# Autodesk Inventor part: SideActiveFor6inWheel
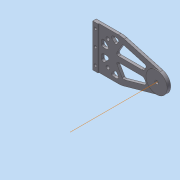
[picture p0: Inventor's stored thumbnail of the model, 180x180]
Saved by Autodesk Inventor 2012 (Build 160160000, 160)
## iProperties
Created: 2011-12
Part Number: SideActiveFor6inWheel
Document SubType Name: Modeling
Designer: OSR
Density: 2.71 g/cm^3
Material: Aluminum-6061
Mass: 81.6285 g
Surface Area: 165.271 cm^2
Volume: 30.1212 cm^3
Author: OSR
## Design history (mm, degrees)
sketch "Sketch1"
  geometry: L1 (0, 0)-(0, 76.2); L2 (0, 76.2)-(44.45, 76.2); L3 (54.781, 74.772)-(119.868, 56.436); L4 (119.868, 19.764)-(54.781, 1.428); L5 (44.45, 0)-(0, 0); L6 (114.702, 38.1)-(0, 38.1); A1 r 19.05 centre (114.702, 38.1) between (119.868, 19.764) and (119.868, 56.436); A2 r 38.1 centre (44.45, 38.1) between (54.781, 74.772) and (44.45, 76.2); A3 r 38.1 centre (44.45, 38.1) between (44.45, 0) and (54.781, 1.428)
  constraints: 12 end point, 6 point on circle, 6 tangent, 3 centre point, 2 parallel, 1 concentric, 1 horizontal, 1 midpoint, 1 perpendicular, 1 vertical
  dimensions: "d0" = 76.2 distance of L1.start L1.end; "d1" = 114.7022 distance of L6.start L6.end; "d2" = 38.1 radius of A2; "d3" = 44.45 distance of L1.end L2.end; "d4" = 38.1 diameter of A1
extrude "Extrusion1" new body sketch "Sketch1" distance "d5" = 6.35; taper "d6" = 0 deg
sketch "Sketch2"
  geometry: L1 (0, 0)-(0, 76.2) reference; L2 (44.45, 0)-(0, 0) reference; L3 (119.868, 19.764)-(54.781, 1.428) reference; L4 (54.781, 74.772)-(119.868, 56.436) reference; L5 (0, 76.2)-(44.45, 76.2) reference; L6 (9.525, 76.2)-(9.525, 0); A1 r 38.1 centre (44.45, 38.1) between (44.45, 0) and (54.781, 1.428) reference; A2 r 19.05 centre (114.702, 38.1) between (119.868, 19.764) and (119.868, 56.436) reference; A3 r 38.1 centre (44.45, 38.1) between (54.781, 74.772) and (44.45, 76.2) reference; 1 further point
  constraints: 2 end point, 2 point on line, 1 coincident, 1 perpendicular, 3 other
  dimensions: "d7" = 9.525 distance between parallel lines of L1 L6
extrude "Extrusion2" cut sketch "Sketch2" distance "d8" = 1.5875; taper "d9" = 0 deg
sketch "Sketch3"
  geometry: L1 (0, 76.2)-(9.525, 76.2) reference; L2 (9.525, 0)-(0, 0) reference; L3 (4.763, 0)-(4.762, 76.2); 3 further points
  constraints: 3 midpoint, 2 end point, 2 point on line
  dimensions: "d10" = 9.525 distance from line of L2 point (4.763, 9.525); "d11" = 9.525 distance from line of L1 point (4.762, 66.675)
hole "Hole1" sketch "Sketch3" at (4.763, 9.525), (4.762, 66.675), (4.763, 38.1) diameter "d12" = 4.8514; stored, may be unused: countersink angle "d16" = 82 deg, drill point angle "d18" = 118 deg; dims "d13" = 19.05, "d14" = 9.525, "d15" = 6.35, "d17" = 25.4
sketch "Sketch4"
  geometry: A1 r 19.05 centre (-114.702, 38.1) between (-119.868, 56.436) and (-119.868, 19.764) reference; 1 further point
  constraints: 1 coincident
hole "Hole2" sketch "Sketch4" at (-114.702, 38.1) diameter "d19" = 6.35; stored, may be unused: countersink angle "d23" = 82 deg, drill point angle "d25" = 118 deg; dims "d20" = 19.05, "d21" = 12.7, "d22" = 3.175, "d24" = 25.4
sketch "Sketch5"
  geometry: L1 (9.525, 76.2)-(9.525, 0) reference; L2 (44.45, 0)-(9.525, 0) reference; L3 (25.4, 60.325)-(25.4, 15.875); L4 (25.4, 38.1)-(9.525, 38.1); L5 (0, 0)-(0, 76.2) reference; L6 (25.4, 60.325)-(23.114, 60.325); L7 (23.114, 60.325)-(23.114, 15.875); L8 (23.114, 15.875)-(25.4, 15.875); L9 (25.4, 15.875)-(25.4, 60.325); 4 further points
  constraints: 12 end point, 4 midpoint, 2 coincident, 2 horizontal, 2 parallel, 2 perpendicular, 1 point on line
  dimensions: "d27" = 44.45 distance of L3.start L3.end; "d63" = 2.286 distance of L3.start L6.end; "d67" = 24.257 distance from line of L5 point (24.257, 60.325)
hole "Hole3" sketch "Sketch5" at (25.4, 60.325), (25.4, 15.875) diameter "d28" = 6.5278; stored, may be unused: countersink angle "d32" = 82 deg, drill point angle "d34" = 118 deg; dims "d29" = 19.05, "d30" = 9.525, "d31" = 6.35, "d33" = 25.4
sketch "Sketch6"
  geometry: L1 (54.781, 74.772)-(119.868, 56.436) reference; L2 (9.525, 76.2)-(9.525, 0) reference; L3 (44.45, 0)-(9.525, 0) reference; L4 (119.868, 19.764)-(54.781, 1.428) reference; L5 (54.781, 11.323)-(92.038, 21.819); L6 (86.661, 33.337)-(44.808, 33.337); L7 (42.058, 28.575)-(51.171, 12.792); L8 (44.808, 42.862)-(86.661, 42.862); L9 (92.038, 54.381)-(54.781, 64.877); L10 (51.171, 63.408)-(42.058, 47.625); L11 (114.702, 38.1)-(9.525, 38.1); L12 (54.781, 11.323)-(54.781, 1.428); L13 (9.525, 76.2)-(44.45, 76.2) reference; L14 (35.488, 6.35)-(41.838, 6.35); L15 (44.698, 11.303)-(42.374, 15.329); L16 (37.179, 16.013)-(33.154, 11.987); L17 (37.179, 60.187)-(33.154, 64.213); L18 (44.698, 64.897)-(42.374, 60.871); L19 (35.488, 69.85)-(41.838, 69.85); L20 (17.59, 33.338)-(23.939, 33.338); L21 (26.274, 27.701)-(19.924, 21.351); L22 (14.288, 23.686)-(14.288, 30.036); L23 (14.288, 52.514)-(14.287, 46.165); L24 (26.274, 48.499)-(19.924, 54.849); L25 (17.59, 42.862)-(23.939, 42.863); A1 r 19.05 centre (114.702, 38.1) between (119.868, 56.436) and (119.868, 19.764) reference; A2 r 23.812 centre (114.702, 38.1) between (93.945, 49.769) and (92.565, 46.873); A3 r 23.812 centre (114.702, 38.1) between (92.565, 29.327) and (93.945, 26.431); A4 r 3.175 centre (53.92, 14.379) between (51.171, 12.792) and (54.781, 11.323); A5 r 3.175 centre (44.808, 30.162) between (44.808, 33.337) and (42.058, 28.575); A6 r 3.175 centre (44.808, 46.037) between (42.058, 47.625) and (44.808, 42.862); A7 r 3.175 centre (53.92, 61.821) between (54.781, 64.877) and (51.171, 63.408); A8 r 6.35 centre (86.661, 26.987) between (92.565, 29.327) and (86.661, 33.337); A9 r 6.35 centre (86.661, 49.212) between (86.661, 42.862) and (92.565, 46.873); A10 r 3.175 centre (91.177, 51.325) between (93.945, 49.769) and (92.038, 54.381); A11 r 3.175 centre (91.177, 24.875) between (92.038, 21.819) and (93.945, 26.431); A12 r 3.302 centre (35.488, 9.652) between (33.154, 11.987) and (35.488, 6.35); A13 r 3.302 centre (39.514, 13.678) between (42.374, 15.329) and (37.179, 16.013); A14 r 3.302 centre (41.838, 9.652) between (41.838, 6.35) and (44.698, 11.303); A15 r 3.302 centre (35.488, 66.548) between (35.488, 69.85) and (33.154, 64.213); A16 r 3.302 centre (39.514, 62.522) between (37.179, 60.187) and (42.374, 60.871); A17 r 3.302 centre (41.838, 66.548) between (44.698, 64.897) and (41.838, 69.85); A18 r 3.302 centre (17.59, 23.686) between (14.288, 23.686) and (19.924, 21.351); A19 r 3.302 centre (17.59, 30.036) between (17.59, 33.338) and (14.288, 30.036); A20 r 3.302 centre (23.939, 30.036) between (26.274, 27.701) and (23.939, 33.338); A21 r 3.302 centre (23.939, 46.165) between (23.939, 42.863) and (26.274, 48.499); A22 r 3.302 centre (17.59, 52.514) between (19.924, 54.849) and (14.288, 52.514); A23 r 3.302 centre (17.589, 46.165) between (14.287, 46.165) and (17.59, 42.862); 5 further points
  constraints: 48 point on circle, 40 end point, 29 tangent, 22 centre point, 18 symmetric about line, 9 equal radius, 7 parallel, 4 point on line, 2 equal length, 2 perpendicular, 1 coincident, 1 midpoint, 1 vertical, 6 other
  dimensions: "d35" = 9.525 distance between parallel lines of L4 L5; "d36" = 9.525 distance between parallel lines of L1 L9; "d37" = 9.525 distance between parallel lines of L6 L8; "d38" = 4.7625 distance between parallel lines of L6 L11; "d39" = 4.7625 radial gap between concentric circles of A1 A3; "d43" = 120 deg angle of L10 L7; "d44" = 3.175 radius of A4; "d47" = 6.35 radius of A8; "d48" = 3.175 radius of A10; "d49" = 3.302 radius of A12; "d50" = 6.35 distance between parallel lines of L7 L15; "d51" = 6.35 distance between parallel lines of L3 L14; "d53" = 6.35 distance of A14.centre A12.centre; "d54" = 45 deg angle of L16 L14; "d55" = 3.302 radius of A18; "d56" = 4.7625 distance between parallel lines of L22 L2; "d57" = 4.7625 distance between parallel lines of L11 L20; "d68" = 6.35 distance of A18.centre A19.centre
extrude "Extrusion3" cut sketch "Sketch6" distance "d45" = 25.4; taper "d46" = 0 deg
workaxis "Work Axis1"
body "Solid1"
